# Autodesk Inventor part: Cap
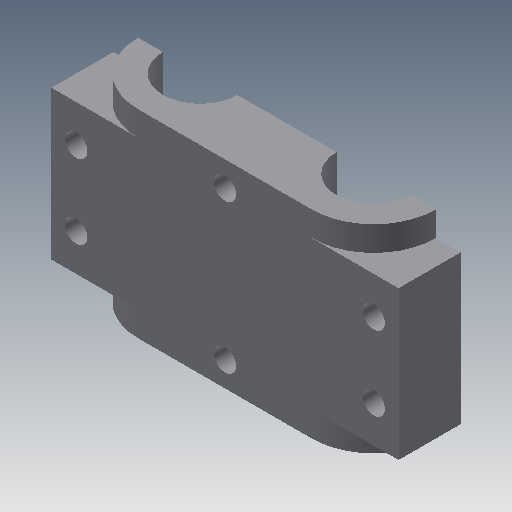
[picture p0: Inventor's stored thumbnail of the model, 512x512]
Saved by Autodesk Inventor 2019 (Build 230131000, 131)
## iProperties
Shininess: 77.0
Length Units: 11269
Angle Units: 11279
Time Units: 11290
Mass Units: 11283
Length Display Precision: 3
Angle Display Precision: 2
Created: 2002-02
Part Number: Cap
Document SubType Name: Modeling
Designer: ***
Density: 1 g/cm^3
Material: Generic
Appearance: Default
Density: 0.0
Volumn: 0.0
Area: 0.0
PropertySet Name: Model Information
Control State: 0
Master: False
Checked Out: False
Author: ***
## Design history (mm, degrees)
sketch "Sketch2"
  geometry: L1 (-17.5, 12.5)-(17.5, 12.5); L2 (30, 0)-(25, 0); L3 (10, 0)-(-10, 0); L4 (-25, 0)-(-30, 0); A1 r 12.5 centre (-17.5, 0) between (-17.5, 12.5) and (-30, 0); A2 r 12.5 centre (17.5, 0) between (30, 0) and (17.5, 12.5); A3 r 7.5 centre (17.5, 0) between (25, 0) and (10, 0); A4 r 7.5 centre (-17.5, 0) between (-10, 0) and (-25, 0)
  constraints: 8 end point, 8 point on circle, 4 centre point, 3 horizontal, 3 parallel, 2 coincident, 2 equal radius, 2 tangent
  dimensions: "d0" = 12.5 radius of A1; "d1" = 7.5 radius of A4; "d2" = 35 distance of A1.centre A2.centre; "d3" = 12.5 distance between parallel lines of L1 L3
extrude "Extrusion1" new body sketch "Sketch2" stored distance "d4" = 40; taper "d5" = 0 deg
workplane "Work Plane1"
sketch "Sketch3"
  geometry: L1 (-15, 12.5)-(15, 12.5); L2 (15, 12.5)-(15, 0); L3 (15, 0)-(-15, 0); L4 (-15, 0)-(-15, 12.5); L5 (-20, 0)-(20, 0) reference; L6 (-20, 12.5)-(20, 12.5) reference; L7 (20, 12.5)-(20, 0) reference
  constraints: 8 end point, 2 collinear, 2 parallel, 1 horizontal, 1 perpendicular
  dimensions: "d7" = 30 distance of L2.end L3.end; "d8" = 5 distance between parallel lines of L7 L2
extrude "Extrusion2" join sketch "Sketch3" stored distance "d9" = 40; taper "d10" = 0 deg
mirror "Mirror1"
sketch "Sketch4"
  geometry: L1 (-17.5, -35)-(0, -35) reference; L2 (-17.5, -35)-(-17.5, -5) reference; 1 further point
  dimensions: "d12" = 7.5 distance from line of L1 point (-12.5, -27.5); "d13" = 5 distance from line of L2 point (-12.5, -27.5)
hole "Hole1" sketch "Sketch4" at (-12.5, -27.5) diameter "d14" = 4.5; stored, may be unused: countersink angle "d18" = 82 deg, drill point angle "d20" = 118 deg; dims "d15" = 6, "d16" = 4, "d17" = 2, "d19" = 8
pattern_linear "Rectangular Pattern1" dims "d23" = 60, "d26" = 15
sketch "Sketch5"
  geometry: L1 (0, -40)-(35, -40) reference; L2 (-17.5, -35)-(-17.5, -5) reference; 1 further point
  dimensions: "d27" = 5 distance from line of L1 point (17.5, -35); "d28" = 35 distance from line of L2 point (17.5, -35)
hole "Hole2" sketch "Sketch5" at (17.5, -35) diameter "d29" = 4.5; stored, may be unused: countersink angle "d33" = 82 deg, drill point angle "d35" = 118 deg; dims "d30" = 6, "d31" = 4, "d32" = 2, "d34" = 8
pattern_linear "Rectangular Pattern2" dims "d38" = 30
body "Solid1"
other parameters: "d11" = 35
